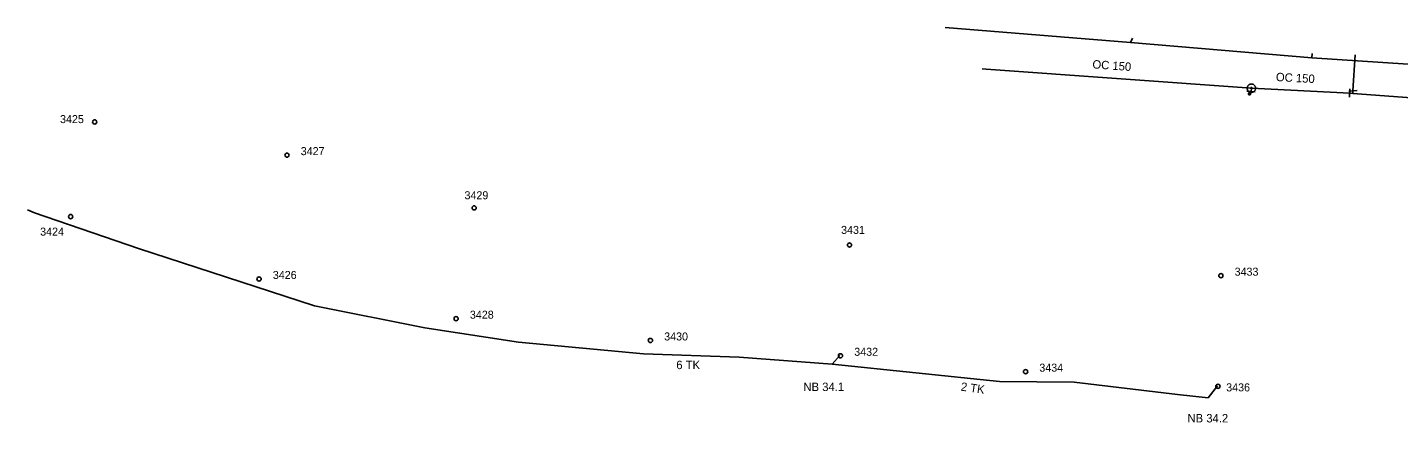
# Model space of a CAD drawing. Extents: x -759784 to -759434, y -974861 to -974639.
# Drawn here: x -759784 to -759621.2, y -974771.1 to -974724.3 of the extents above; entities that cross this region are included whole.
import ezdxf

# ---------------------------------------------------------------- set-up
doc = ezdxf.new("R2010")
doc.units = 0
for name, color, linetype in [('IS_CETIN_sdělovací kabel_podzemní', 7, 'Continuous'), ('IS_DpmUL_kabel', 7, 'Continuous'), ('IS_DpmUL_stožáry', 7, 'Continuous'), ('IS_popis_DpmUL', 7, 'Continuous'), ('IS_popis_ScVK', 7, 'Continuous'), ('IS_ScVK_Kanal', 7, 'Continuous'), ('IS_ScVK_Vodovod', 7, 'Continuous')]:
    doc.layers.add(name, color=color, linetype=linetype)

msp = doc.modelspace()

# ---------------------------------------------------------------- linework, layer by layer
at = {"layer": 'IS_CETIN_sdělovací kabel_podzemní'}
for points in [[(-759675.04, -974724.28), (-759653.01, -974726.05)], [(-759653.01, -974726.05), (-759652.77, -974725.56)], [(-759653.01, -974726.05), (-759631.51, -974727.87)], [(-759631.51, -974727.87), (-759631.47, -974727.36)], [(-759631.51, -974727.87), (-759620.07, -974728.63), (-759617.45, -974727.82), (-759609.42, -974728.47)]]:
    msp.add_lwpolyline(points, dxfattribs=at)
at = {"layer": 'IS_DpmUL_kabel'}
for points in [[(-759783.956, -974745.923), (-759783.118, -974746.243), (-759770.788, -974750.503), (-759749.868, -974757.283)], [(-759749.868, -974757.283), (-759736.778, -974759.883), (-759725.648, -974761.583), (-759710.848, -974762.963), (-759699.488, -974763.363), (-759688.448, -974764.223), (-759687.508, -974763.173)], [(-759688.448, -974764.223), (-759668.588, -974766.253), (-759659.708, -974766.323), (-759647.448, -974767.803), (-759643.808, -974768.203), (-759642.698, -974766.773)]]:
    msp.add_lwpolyline(points, dxfattribs=at)
at = {"layer": 'IS_DpmUL_stožáry'}
for centre in [(-759775.968, -974735.483), (-759753.148, -974739.423), (-759778.828, -974746.703), (-759730.928, -974745.673), (-759686.378, -974750.073), (-759756.458, -974754.103), (-759642.298, -974753.713), (-759733.068, -974758.813), (-759710.008, -974761.393), (-759687.448, -974763.213), (-759665.478, -974765.093), (-759642.648, -974766.833)]:
    msp.add_circle(centre, 0.25, dxfattribs=at)
at = {"layer": 'IS_ScVK_Kanal'}
for points in [[(-759638.899, -974732.149), (-759638.708, -974731.879)], [(-759638.678, -974731.483), (-759638.708, -974731.879)], [(-759626.633, -974732.092), (-759626.619, -974731.779)]]:
    msp.add_lwpolyline(points, dxfattribs=at)
at = {"layer": 'IS_ScVK_Vodovod'}
for points in [[(-759626.619, -974731.779), (-759626.375, -974727.545)], [(-759670.62, -974729.187), (-759670.166, -974729.212), (-759638.678, -974731.483)], [(-759639.206, -974731.837), (-759638.209, -974731.921)], [(-759638.18, -974731.53), (-759638.178, -974731.478), (-759638.181, -974731.425), (-759638.19, -974731.374), (-759638.203, -974731.324), (-759638.223, -974731.275), (-759638.247, -974731.228), (-759638.277, -974731.185), (-759638.31, -974731.145), (-759638.347, -974731.108), (-759638.388, -974731.075), (-759638.432, -974731.047), (-759638.479, -974731.024), (-759638.528, -974731.006), (-759638.579, -974730.993), (-759638.63, -974730.985), (-759638.682, -974730.983), (-759638.735, -974730.986), (-759638.787, -974730.995), (-759638.836, -974731.008), (-759638.885, -974731.028), (-759638.932, -974731.052), (-759638.976, -974731.081), (-759639.016, -974731.115), (-759639.053, -974731.152), (-759639.085, -974731.193), (-759639.113, -974731.237), (-759639.137, -974731.284), (-759639.154, -974731.333), (-759639.167, -974731.384), (-759639.175, -974731.435), (-759639.177, -974731.487), (-759639.174, -974731.54), (-759639.166, -974731.592), (-759639.152, -974731.641), (-759639.132, -974731.69), (-759639.108, -974731.737), (-759639.08, -974731.781), (-759639.046, -974731.821), (-759639.008, -974731.858), (-759638.967, -974731.89), (-759638.923, -974731.918), (-759638.877, -974731.942), (-759638.827, -974731.959), (-759638.776, -974731.972), (-759638.725, -974731.98), (-759638.673, -974731.982), (-759638.62, -974731.979), (-759638.569, -974731.971), (-759638.519, -974731.957), (-759638.47, -974731.937), (-759638.423, -974731.913), (-759638.38, -974731.884), (-759638.34, -974731.851), (-759638.303, -974731.813), (-759638.27, -974731.772), (-759638.242, -974731.728), (-759638.219, -974731.682), (-759638.201, -974731.632), (-759638.188, -974731.581), (-759638.18, -974731.53)], [(-759639.025, -974732.149), (-759639.025, -974732.162), (-759639.022, -974732.175), (-759639.02, -974732.188), (-759639.015, -974732.2), (-759639.009, -974732.212), (-759639.002, -974732.223), (-759638.994, -974732.233), (-759638.983, -974732.243), (-759638.973, -974732.251), (-759638.963, -974732.258), (-759638.951, -974732.264), (-759638.939, -974732.269), (-759638.926, -974732.272), (-759638.913, -974732.274), (-759638.9, -974732.276), (-759638.887, -974732.275), (-759638.874, -974732.273), (-759638.861, -974732.27), (-759638.848, -974732.265), (-759638.837, -974732.259), (-759638.826, -974732.252), (-759638.816, -974732.244), (-759638.806, -974732.234), (-759638.798, -974732.224), (-759638.791, -974732.213), (-759638.785, -974732.201), (-759638.78, -974732.189), (-759638.777, -974732.176), (-759638.775, -974732.163), (-759638.772, -974732.15), (-759638.774, -974732.137), (-759638.776, -974732.124), (-759638.779, -974732.111), (-759638.784, -974732.099), (-759638.789, -974732.087), (-759638.797, -974732.076), (-759638.804, -974732.066), (-759638.815, -974732.056), (-759638.825, -974732.048), (-759638.836, -974732.041), (-759638.848, -974732.035), (-759638.86, -974732.03), (-759638.873, -974732.027), (-759638.886, -974732.025), (-759638.899, -974732.024), (-759638.912, -974732.024), (-759638.924, -974732.026), (-759638.938, -974732.029), (-759638.95, -974732.034), (-759638.962, -974732.04), (-759638.973, -974732.047), (-759638.983, -974732.055), (-759638.993, -974732.065), (-759639, -974732.075), (-759639.008, -974732.086), (-759639.014, -974732.098), (-759639.019, -974732.11), (-759639.022, -974732.123), (-759639.024, -974732.136), (-759639.025, -974732.149)], [(-759639.005, -974732.149), (-759639.005, -974732.16), (-759639.004, -974732.171), (-759639, -974732.182), (-759638.997, -974732.192), (-759638.992, -974732.202), (-759638.986, -974732.211), (-759638.978, -974732.22), (-759638.971, -974732.228), (-759638.962, -974732.235), (-759638.953, -974732.241), (-759638.943, -974732.246), (-759638.933, -974732.25), (-759638.922, -974732.253), (-759638.911, -974732.256), (-759638.9, -974732.256), (-759638.889, -974732.256), (-759638.878, -974732.254), (-759638.867, -974732.251), (-759638.857, -974732.247), (-759638.847, -974732.242), (-759638.838, -974732.236), (-759638.829, -974732.229), (-759638.821, -974732.221), (-759638.814, -974732.212), (-759638.808, -974732.203), (-759638.803, -974732.193), (-759638.799, -974732.183), (-759638.796, -974732.172), (-759638.794, -974732.161), (-759638.793, -974732.15), (-759638.793, -974732.139), (-759638.794, -974732.128), (-759638.798, -974732.117), (-759638.802, -974732.107), (-759638.807, -974732.097), (-759638.813, -974732.088), (-759638.82, -974732.079), (-759638.828, -974732.071), (-759638.837, -974732.064), (-759638.846, -974732.058), (-759638.856, -974732.053), (-759638.865, -974732.049), (-759638.877, -974732.046), (-759638.887, -974732.044), (-759638.899, -974732.044), (-759638.91, -974732.043), (-759638.921, -974732.045), (-759638.932, -974732.048), (-759638.941, -974732.052), (-759638.951, -974732.057), (-759638.961, -974732.063), (-759638.97, -974732.07), (-759638.978, -974732.078), (-759638.985, -974732.087), (-759638.99, -974732.096), (-759638.995, -974732.106), (-759639, -974732.116), (-759639.003, -974732.127), (-759639.005, -974732.138), (-759639.005, -974732.149)], [(-759638.986, -974732.149), (-759638.986, -974732.158), (-759638.985, -974732.167), (-759638.982, -974732.176), (-759638.978, -974732.184), (-759638.975, -974732.192), (-759638.97, -974732.2), (-759638.963, -974732.207), (-759638.958, -974732.213), (-759638.951, -974732.219), (-759638.943, -974732.224), (-759638.934, -974732.228), (-759638.927, -974732.231), (-759638.918, -974732.234), (-759638.909, -974732.235), (-759638.9, -974732.237), (-759638.891, -974732.236), (-759638.882, -974732.235), (-759638.873, -974732.232), (-759638.865, -974732.229), (-759638.857, -974732.225), (-759638.848, -974732.22), (-759638.842, -974732.214), (-759638.836, -974732.208), (-759638.83, -974732.201), (-759638.825, -974732.193), (-759638.821, -974732.185), (-759638.818, -974732.177), (-759638.815, -974732.168), (-759638.814, -974732.159), (-759638.811, -974732.15), (-759638.813, -974732.141), (-759638.814, -974732.132), (-759638.816, -974732.123), (-759638.82, -974732.115), (-759638.824, -974732.107), (-759638.829, -974732.099), (-759638.835, -974732.092), (-759638.841, -974732.086), (-759638.848, -974732.08), (-759638.856, -974732.075), (-759638.864, -974732.071), (-759638.872, -974732.068), (-759638.88, -974732.065), (-759638.89, -974732.064), (-759638.899, -974732.063), (-759638.907, -974732.063), (-759638.917, -974732.064), (-759638.926, -974732.067), (-759638.934, -974732.07), (-759638.941, -974732.074), (-759638.95, -974732.079), (-759638.956, -974732.085), (-759638.963, -974732.091), (-759638.968, -974732.098), (-759638.973, -974732.106), (-759638.978, -974732.114), (-759638.981, -974732.122), (-759638.983, -974732.131), (-759638.985, -974732.14), (-759638.986, -974732.149)], [(-759638.596, -974731.49), (-759638.595, -974731.481), (-759638.596, -974731.473), (-759638.597, -974731.465), (-759638.6, -974731.457), (-759638.603, -974731.448), (-759638.607, -974731.441), (-759638.612, -974731.434), (-759638.617, -974731.427), (-759638.623, -974731.421), (-759638.63, -974731.416), (-759638.638, -974731.411), (-759638.645, -974731.407), (-759638.653, -974731.404), (-759638.661, -974731.402), (-759638.67, -974731.401), (-759638.679, -974731.4), (-759638.687, -974731.401), (-759638.695, -974731.402), (-759638.703, -974731.405), (-759638.712, -974731.408), (-759638.719, -974731.412), (-759638.726, -974731.417), (-759638.733, -974731.422), (-759638.74, -974731.428), (-759638.744, -974731.435), (-759638.749, -974731.443), (-759638.753, -974731.45), (-759638.756, -974731.458), (-759638.758, -974731.466), (-759638.759, -974731.475), (-759638.76, -974731.484), (-759638.759, -974731.492), (-759638.758, -974731.5), (-759638.755, -974731.508), (-759638.752, -974731.517), (-759638.749, -974731.524), (-759638.743, -974731.531), (-759638.738, -974731.538), (-759638.732, -974731.545), (-759638.725, -974731.549), (-759638.717, -974731.554), (-759638.71, -974731.558), (-759638.702, -974731.561), (-759638.694, -974731.563), (-759638.685, -974731.564), (-759638.676, -974731.565), (-759638.668, -974731.564), (-759638.66, -974731.563), (-759638.652, -974731.56), (-759638.643, -974731.557), (-759638.636, -974731.554), (-759638.629, -974731.548), (-759638.622, -974731.543), (-759638.616, -974731.537), (-759638.611, -974731.53), (-759638.606, -974731.522), (-759638.602, -974731.515), (-759638.599, -974731.507), (-759638.597, -974731.499), (-759638.596, -974731.49)], [(-759638.678, -974731.483), (-759626.999, -974732.058)], [(-759627.117, -974731.817), (-759626.12, -974731.741)], [(-759626.977, -974731.558), (-759627.021, -974732.557)], [(-759626.999, -974732.058), (-759626.633, -974732.092), (-759582.234, -974735.394), (-759581.903, -974735.393)], [(-759638.966, -974732.149), (-759638.966, -974732.156), (-759638.965, -974732.163), (-759638.963, -974732.17), (-759638.961, -974732.176), (-759638.958, -974732.182), (-759638.954, -974732.188), (-759638.95, -974732.194), (-759638.945, -974732.199), (-759638.939, -974732.203), (-759638.933, -974732.207), (-759638.927, -974732.21), (-759638.921, -974732.213), (-759638.914, -974732.214), (-759638.907, -974732.217), (-759638.9, -974732.217), (-759638.892, -974732.217), (-759638.886, -974732.215), (-759638.879, -974732.214), (-759638.873, -974732.211), (-759638.865, -974732.208), (-759638.861, -974732.204), (-759638.855, -974732.2), (-759638.85, -974732.195), (-759638.846, -974732.189), (-759638.842, -974732.183), (-759638.838, -974732.177), (-759638.836, -974732.171), (-759638.834, -974732.164), (-759638.833, -974732.157), (-759638.831, -974732.15), (-759638.831, -974732.143), (-759638.833, -974732.136), (-759638.835, -974732.129), (-759638.838, -974732.123), (-759638.841, -974732.116), (-759638.845, -974732.111), (-759638.848, -974732.105), (-759638.853, -974732.1), (-759638.86, -974732.096), (-759638.865, -974732.092), (-759638.872, -974732.089), (-759638.878, -974732.086), (-759638.885, -974732.084), (-759638.892, -974732.083), (-759638.899, -974732.083), (-759638.906, -974732.083), (-759638.913, -974732.083), (-759638.919, -974732.085), (-759638.926, -974732.088), (-759638.932, -974732.091), (-759638.938, -974732.095), (-759638.944, -974732.099), (-759638.949, -974732.104), (-759638.953, -974732.11), (-759638.956, -974732.115), (-759638.96, -974732.122), (-759638.963, -974732.128), (-759638.963, -974732.135), (-759638.966, -974732.142), (-759638.966, -974732.149)], [(-759638.946, -974732.149), (-759638.946, -974732.154), (-759638.946, -974732.159), (-759638.945, -974732.164), (-759638.943, -974732.168), (-759638.941, -974732.173), (-759638.938, -974732.177), (-759638.934, -974732.18), (-759638.931, -974732.184), (-759638.928, -974732.187), (-759638.924, -974732.19), (-759638.919, -974732.192), (-759638.914, -974732.194), (-759638.91, -974732.195), (-759638.905, -974732.197), (-759638.9, -974732.197), (-759638.895, -974732.197), (-759638.89, -974732.196), (-759638.885, -974732.195), (-759638.88, -974732.193), (-759638.875, -974732.191), (-759638.872, -974732.188), (-759638.868, -974732.185), (-759638.865, -974732.181), (-759638.862, -974732.178), (-759638.858, -974732.174), (-759638.857, -974732.169), (-759638.855, -974732.165), (-759638.853, -974732.16), (-759638.853, -974732.155), (-759638.852, -974732.15), (-759638.852, -974732.145), (-759638.853, -974732.14), (-759638.853, -974732.135), (-759638.856, -974732.131), (-759638.858, -974732.126), (-759638.861, -974732.122), (-759638.864, -974732.118), (-759638.867, -974732.115), (-759638.87, -974732.112), (-759638.875, -974732.109), (-759638.88, -974732.107), (-759638.884, -974732.105), (-759638.889, -974732.104), (-759638.894, -974732.103), (-759638.899, -974732.103), (-759638.904, -974732.103), (-759638.909, -974732.104), (-759638.914, -974732.104), (-759638.918, -974732.106), (-759638.923, -974732.108), (-759638.927, -974732.111), (-759638.929, -974732.114), (-759638.934, -974732.117), (-759638.936, -974732.121), (-759638.94, -974732.125), (-759638.941, -974732.13), (-759638.944, -974732.134), (-759638.945, -974732.139), (-759638.946, -974732.144), (-759638.946, -974732.149)], [(-759638.926, -974732.149), (-759638.926, -974732.152), (-759638.927, -974732.155), (-759638.926, -974732.157), (-759638.924, -974732.16), (-759638.924, -974732.163), (-759638.922, -974732.165), (-759638.919, -974732.167), (-759638.918, -974732.169), (-759638.916, -974732.171), (-759638.914, -974732.173), (-759638.911, -974732.175), (-759638.907, -974732.176), (-759638.906, -974732.176), (-759638.902, -974732.177), (-759638.9, -974732.177), (-759638.897, -974732.177), (-759638.894, -974732.177), (-759638.891, -974732.176), (-759638.889, -974732.175), (-759638.886, -974732.174), (-759638.884, -974732.172), (-759638.88, -974732.17), (-759638.879, -974732.168), (-759638.878, -974732.166), (-759638.875, -974732.164), (-759638.875, -974732.161), (-759638.873, -974732.158), (-759638.873, -974732.156), (-759638.872, -974732.153), (-759638.87, -974732.15), (-759638.872, -974732.147), (-759638.872, -974732.144), (-759638.873, -974732.141), (-759638.874, -974732.139), (-759638.875, -974732.136), (-759638.877, -974732.134), (-759638.878, -974732.131), (-759638.88, -974732.129), (-759638.883, -974732.128), (-759638.885, -974732.126), (-759638.887, -974732.125), (-759638.89, -974732.124), (-759638.892, -974732.123), (-759638.896, -974732.123), (-759638.899, -974732.122), (-759638.902, -974732.123), (-759638.905, -974732.122), (-759638.907, -974732.124), (-759638.91, -974732.124), (-759638.913, -974732.125), (-759638.914, -974732.127), (-759638.917, -974732.128), (-759638.919, -974732.13), (-759638.921, -974732.133), (-759638.923, -974732.135), (-759638.924, -974732.138), (-759638.924, -974732.14), (-759638.926, -974732.143), (-759638.926, -974732.146), (-759638.926, -974732.149)], [(-759638.907, -974732.149), (-759638.907, -974732.151), (-759638.907, -974732.151), (-759638.906, -974732.151), (-759638.906, -974732.153), (-759638.907, -974732.154), (-759638.905, -974732.154), (-759638.905, -974732.154), (-759638.905, -974732.156), (-759638.905, -974732.156), (-759638.904, -974732.157), (-759638.902, -974732.157), (-759638.902, -974732.157), (-759638.902, -974732.158), (-759638.9, -974732.158), (-759638.9, -974732.158), (-759638.899, -974732.158), (-759638.897, -974732.158), (-759638.897, -974732.157), (-759638.897, -974732.157), (-759638.895, -974732.157), (-759638.895, -974732.156), (-759638.895, -974732.156), (-759638.894, -974732.155), (-759638.894, -974732.155), (-759638.892, -974732.154), (-759638.892, -974732.153), (-759638.891, -974732.152), (-759638.891, -974732.152), (-759638.891, -974732.151), (-759638.891, -974732.15), (-759638.891, -974732.149), (-759638.891, -974732.148), (-759638.891, -974732.148), (-759638.892, -974732.147), (-759638.892, -974732.146), (-759638.892, -974732.145), (-759638.892, -974732.145), (-759638.894, -974732.144), (-759638.894, -974732.144), (-759638.895, -974732.143), (-759638.896, -974732.143), (-759638.897, -974732.142), (-759638.897, -974732.142), (-759638.897, -974732.142), (-759638.899, -974732.142), (-759638.9, -974732.142), (-759638.901, -974732.142), (-759638.901, -974732.142), (-759638.902, -974732.143), (-759638.902, -974732.142), (-759638.904, -974732.144), (-759638.904, -974732.144), (-759638.905, -974732.144), (-759638.905, -974732.144), (-759638.906, -974732.146), (-759638.906, -974732.147), (-759638.906, -974732.148), (-759638.907, -974732.148), (-759638.907, -974732.149), (-759638.907, -974732.149)]]:
    msp.add_lwpolyline(points, dxfattribs=at)

# ---------------------------------------------------------------- texts
at = {"layer": 'IS_popis_DpmUL'}
for s, height, p in [('3425', 0.95, (-759780.085, -974735.622)), ('3427', 0.95, (-759751.515, -974739.422)), ('3429', 0.95, (-759732.075, -974744.652)), ('3424', 0.95, (-759782.445, -974748.962)), ('3431', 0.95, (-759687.375, -974748.762)), ('3426', 0.95, (-759754.825, -974754.102)), ('3433', 0.95, (-759640.665, -974753.712)), ('3428', 0.95, (-759731.435, -974758.812)), ('3430', 0.95, (-759708.375, -974761.392)), ('3432', 0.95, (-759685.815, -974763.212)), ('6 TK', 1, (-759706.938, -974764.792)), ('3434', 0.95, (-759663.845, -974765.092)), ('NB 34.1', 1, (-759691.848, -974767.392)), ('3436', 0.95, (-759641.665, -974767.432)), ('NB 34.2', 1, (-759646.258, -974771.112))]:
    msp.add_text(s, height=height, dxfattribs=at).set_placement(p)
msp.add_text('2 TK', height=1, rotation=351.96797, dxfattribs=at).set_placement((-759673.21, -974767.332))
at = {"layer": 'IS_popis_ScVK'}
for rotation, p in [(356, (-759657.57, -974729.128)), (357, (-759635.786, -974730.638))]:
    msp.add_text('OC 150', height=1, rotation=rotation, dxfattribs=at).set_placement(p)

doc.saveas('drawing.dxf')
